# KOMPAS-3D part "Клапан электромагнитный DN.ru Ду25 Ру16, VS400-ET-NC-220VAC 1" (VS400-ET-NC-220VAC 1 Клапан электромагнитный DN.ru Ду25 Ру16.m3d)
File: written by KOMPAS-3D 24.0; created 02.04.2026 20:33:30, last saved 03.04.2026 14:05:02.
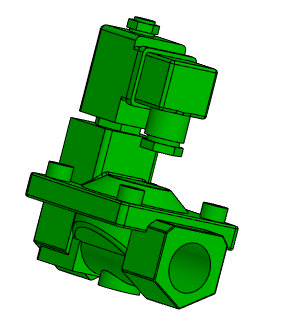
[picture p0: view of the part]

Document properties: Автор: artio; Полное имя файла: C:\Users\artio\OneDrive\Рабочий стол\Клапан электромагнитный DN.ru\VS400-ET-NC-220VAC 1 Клапан электромагнитный DN.ru Ду25 Ру16.m3d

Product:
- Body: Тело 1  | qty 1
    Масса: 1.76797
- Part/product: Клапан электромагнитный DN.ru Ду25 Ру16  | designation VS400-ET-NC-220VAC 1
    Масса: 1.524
    Раздел спецификации: Прочие изделия
    Примечание: D130-04693
    additional columns: ef56311e-7521-43dc-8291-0e6108b3d81d; VS400-ET-NC-220VAC 1; artio; c; Шероховатость не задана; Да

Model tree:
1. Операция без истории:1

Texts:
  VS400-ET-NC-220VAC 1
